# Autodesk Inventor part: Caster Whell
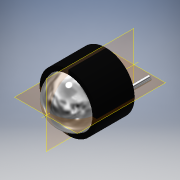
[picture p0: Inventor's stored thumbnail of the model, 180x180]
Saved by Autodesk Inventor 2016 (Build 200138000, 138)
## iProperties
Created: 2016-07
Part Number: Caster Whell
Material: Generic
Document SubType Name: Modeling
Designer: Admin
Density: 1 g/cm^3
Appearance: Default
Author: Admin
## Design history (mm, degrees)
sketch "Sketch1"
  geometry: C1 r 11.062 at (0, 0); 1 further point
  constraints: 1 centre point, 1 coincident
  dimensions: "d0" = 22.1234 diameter of C1
extrude "Extrusion1" new body sketch "Sketch1" distance "d1" = 14.605; taper "d2" = 0 deg
sketch "Sketch2"
  geometry: C1 r 9.335 at (0, 0); 1 further point
  constraints: 1 centre point, 1 coincident
  dimensions: "d3" = 18.669 diameter of C1
extrude "Extrusion2" cut sketch "Sketch2" distance "d4" = 12.7; taper "d5" = 0 deg
sketch "Sketch3"
  geometry: C1 r 5.588 at (0, 0); 1 further point
  constraints: 1 centre point, 1 coincident
  dimensions: "d6" = 11.176 diameter of C1
extrude "Extrusion3" cut sketch "Sketch3" stored distance "d7" = 12.7; taper "d8" = 0 deg
workplane "Work Plane2"
  workplane "Work Plane1"
sketch "Sketch4"
  geometry: L1 (9.525, 0)-(-9.525, 0); A1 r 9.525 centre (0, 0) between (9.525, 0) and (-9.525, 0); 1 further point
  constraints: 2 end point, 2 point on circle, 1 centre point, 1 coincident, 1 horizontal
  dimensions: "d11" = 19.05 diameter of A1
revolve "Revolution1" sketch "Sketch4" stored, may be unused: angle "d12" = 90 deg
sketch "Sketch5"
  geometry: L1 (9.335, 0)-(5.588, 0); L2 (0, 0)-(0, -12.985); C1 r 0.889 at (-7.461, 0); C2 r 0.889 at (7.461, 0); 2 further points
  constraints: 4 end point, 2 centre point, 2 horizontal alignment, 1 equal radius, 1 horizontal, 1 midpoint, 1 point on line, 1 vertical, 3 other
  dimensions: "d14" = 1.778 diameter of C2
extrude "Extrusion4" join sketch "Sketch5" distance "d15" = 9.271; taper "d16" = 0 deg
workaxis "Work Axis1"
workplane "Work Plane3"
workplane "Work Plane5"
  workplane "Work Plane4"
body "Solid1"
other parameters: "d9" = -2.6162, "d10" = -9.525, "d17" = 0, "d18" = 0
